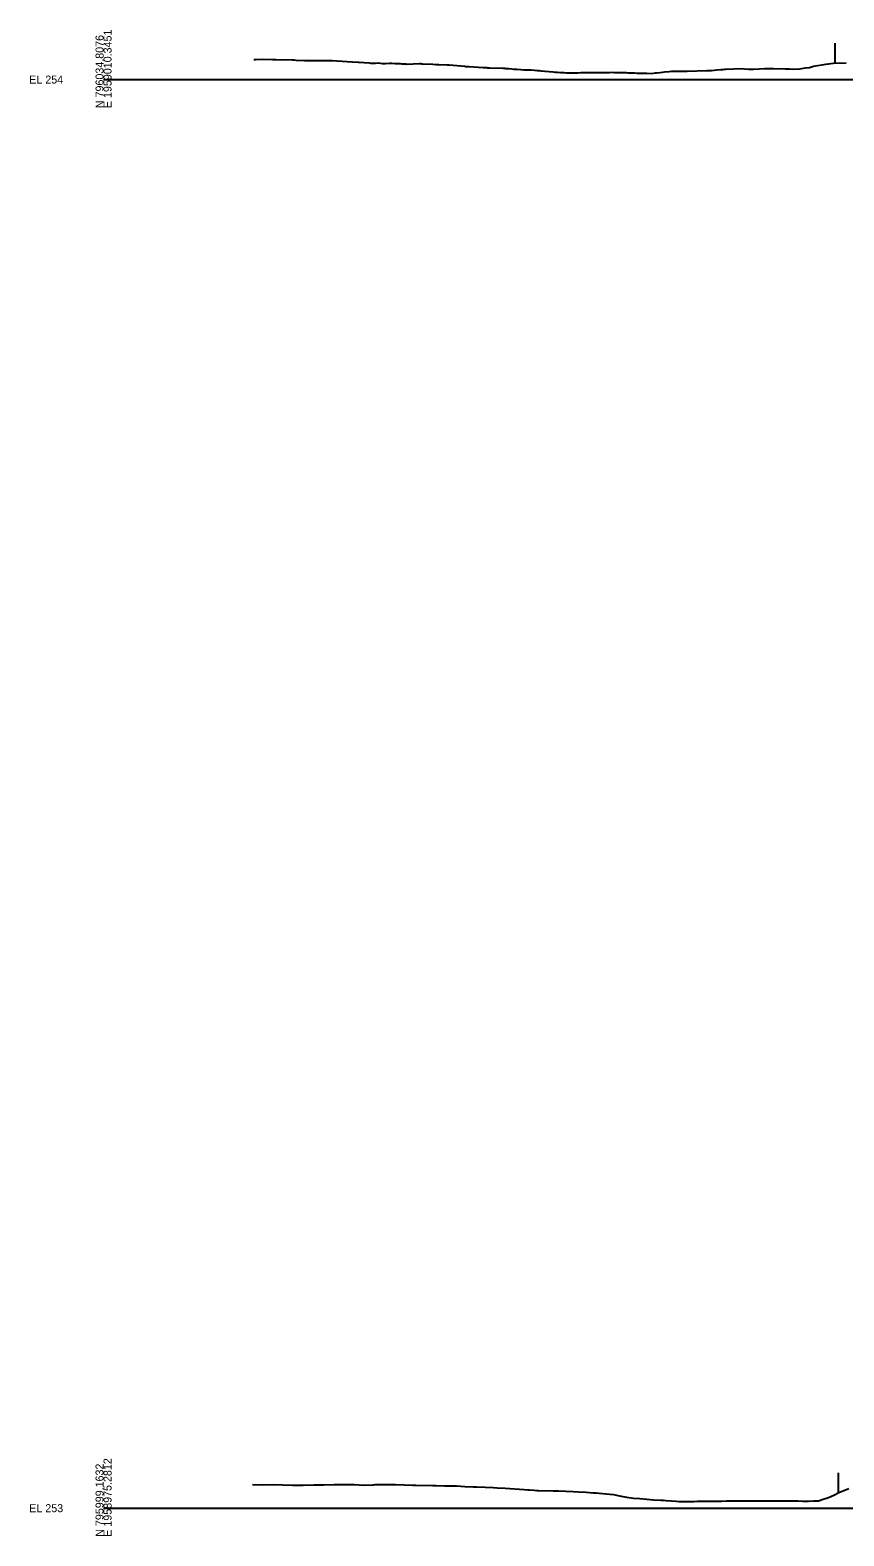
# Model space of a CAD drawing. Extents: x -4026 to 9638, y -10 to 19609.
# Drawn here: x -2026 to -1741, y 14990 to 15517 of the extents above; entities that cross this region are included whole.
import ezdxf

# ---------------------------------------------------------------- set-up
doc = ezdxf.new("R2010")
doc.units = 0
for name, color, linetype in [('Default', 7, 'Continuous'), ('RD_EX_Fence_Other', 7, 'Continuous'), ('RD_GPK_XS_Cell', 7, 'Continuous'), ('RD_XS_ExGround', 7, 'Continuous')]:
    doc.layers.add(name, color=color, linetype=linetype)

msp = doc.modelspace()

# ---------------------------------------------------------------- linework, layer by layer
at = {"layer": 'RD_EX_Fence_Other'}
for p, q in [((-1744.15, 15512.69), (-1744.15, 15505.69)), ((-1742.96, 15012.37), (-1742.96, 15005.37))]:
    msp.add_line(p, q, dxfattribs=at)
at = {"layer": 'RD_GPK_XS_Cell'}
for p, q in [((-2000, 15500), (-1650, 15500)), ((-2000, 15000), (-1650, 15000))]:
    msp.add_line(p, q, dxfattribs=at)
at = {"layer": 'RD_XS_ExGround'}
for points in [[(-1947.42, 15507.05), (-1946.87, 15507.06), (-1943.88, 15507.11), (-1940.94, 15507.03), (-1940.34, 15507.02), (-1939.74, 15507), (-1933.92, 15506.85), (-1933.27, 15506.87), (-1932.61, 15506.79), (-1929.74, 15506.72), (-1926.91, 15506.65), (-1926.2, 15506.65), (-1925.48, 15506.67), (-1919.9, 15506.61), (-1918.35, 15506.53), (-1912.88, 15506.24), (-1910.96, 15506.14), (-1910.57, 15506.09), (-1907.05, 15505.81), (-1906.57, 15505.76), (-1905.78, 15505.75), (-1904.86, 15505.74), (-1903.78, 15505.81), (-1902.5, 15505.63), (-1902.16, 15505.62), (-1901.35, 15505.64), (-1900.05, 15505.7), (-1899.14, 15505.72), (-1897.96, 15505.61), (-1896.98, 15505.59), (-1896.2, 15505.65), (-1895.57, 15505.55), (-1895.03, 15505.53), (-1894.58, 15505.49), (-1894.19, 15505.48), (-1893.86, 15505.44), (-1889.49, 15505.59), (-1889.03, 15505.58), (-1888.63, 15505.52), (-1888.26, 15505.52), (-1884.83, 15505.42), (-1883.77, 15505.32), (-1882.7, 15505.3), (-1879.73, 15505.15), (-1879.43, 15505.13), (-1879.12, 15505.11), (-1873.58, 15504.63), (-1873.28, 15504.61), (-1872.97, 15504.6), (-1872.66, 15504.59), (-1872.34, 15504.57), (-1872.01, 15504.56), (-1867.19, 15504.22), (-1866.89, 15504.2), (-1866.58, 15504.19), (-1866.25, 15504.17), (-1865.92, 15504.16), (-1865.59, 15504.15), (-1865.24, 15504.14), (-1864.88, 15504.13), (-1860.24, 15503.96), (-1859.91, 15503.94), (-1859.58, 15503.93), (-1859.23, 15503.91), (-1858.88, 15503.9), (-1858.51, 15503.85), (-1858.13, 15503.81), (-1857.08, 15503.73), (-1856.39, 15503.64), (-1855.43, 15503.59), (-1853.99, 15503.48), (-1852.91, 15503.41), (-1852.04, 15503.43), (-1850.34, 15503.39), (-1849.2, 15503.28), (-1848.3, 15503.14), (-1847.56, 15503.11), (-1846.94, 15503.09), (-1842.65, 15502.7), (-1841.97, 15502.64), (-1841.15, 15502.58), (-1840.13, 15502.5), (-1838.84, 15502.44), (-1838.03, 15502.36), (-1837.25, 15502.36), (-1835.67, 15502.36), (-1834.44, 15502.39), (-1834.08, 15502.39), (-1833, 15502.41), (-1832.5, 15502.42), (-1831.56, 15502.44), (-1830.92, 15502.44), (-1830.12, 15502.43), (-1829.33, 15502.43), (-1828.68, 15502.45), (-1827.75, 15502.48), (-1827.24, 15502.48), (-1826.16, 15502.49), (-1825.8, 15502.49), (-1824.36, 15502.5), (-1822.92, 15502.52), (-1822.29, 15502.53), (-1821.44, 15502.5), (-1819.78, 15502.48), (-1818.58, 15502.45), (-1818.17, 15502.44), (-1817.13, 15502.43), (-1816.56, 15502.4), (-1815.69, 15502.38), (-1814.96, 15502.34), (-1814.25, 15502.32), (-1813.35, 15502.29), (-1812.81, 15502.28), (-1811.74, 15502.24), (-1811.37, 15502.23), (-1809.93, 15502.2), (-1808.33, 15502.17), (-1806.9, 15502.36), (-1806.51, 15502.38), (-1805.28, 15502.51), (-1804.43, 15502.61), (-1803.67, 15502.69), (-1802.07, 15502.84), (-1801.27, 15502.92), (-1799.91, 15502.91), (-1798.32, 15502.92), (-1797.45, 15502.91), (-1796.88, 15502.91), (-1795.82, 15502.91), (-1788.89, 15503.13), (-1787.22, 15503.19), (-1785.46, 15503.36), (-1783.99, 15503.5), (-1783.16, 15503.56), (-1782.63, 15503.61), (-1782.26, 15503.65), (-1779.62, 15503.79), (-1777.7, 15503.83), (-1775.76, 15503.7), (-1774.17, 15503.67), (-1772.61, 15503.67), (-1770.63, 15503.74), (-1768.63, 15503.84), (-1765.59, 15503.85), (-1761.5, 15503.71), (-1760.03, 15503.72), (-1758.58, 15503.69), (-1756.49, 15503.75), (-1754.37, 15504.09), (-1752.96, 15504.26), (-1751.57, 15504.66), (-1747.24, 15505.37), (-1744.55, 15505.68), (-1740.11, 15505.81)], [(-1947.83, 15008.33), (-1944.29, 15008.22), (-1940.66, 15008.26), (-1933.83, 15008.08), (-1933.53, 15008.07), (-1930.15, 15008.06), (-1926.4, 15008.19), (-1923.08, 15008.15), (-1919.27, 15008.26), (-1912.79, 15008.29), (-1912.14, 15008.27), (-1908.93, 15008.04), (-1905.78, 15008.2), (-1905.4, 15008.23), (-1905.01, 15008.24), (-1901.86, 15008.25), (-1898.77, 15008.28), (-1898.33, 15008.27), (-1897.88, 15008.26), (-1894.79, 15008.2), (-1891.75, 15008.08), (-1890.75, 15008.05), (-1884.74, 15007.95), (-1884.18, 15007.94), (-1883.62, 15007.93), (-1880.65, 15007.85), (-1877.72, 15007.83), (-1876.49, 15007.79), (-1873.58, 15007.64), (-1870.71, 15007.5), (-1870.04, 15007.47), (-1869.36, 15007.44), (-1866.51, 15007.37), (-1863.7, 15007.22), (-1862.23, 15007.15), (-1859.44, 15007.05), (-1852.83, 15006.57), (-1851.53, 15006.45), (-1850.93, 15006.41), (-1849.34, 15006.28), (-1848.39, 15006.23), (-1847.75, 15006.19), (-1842.66, 15006.06), (-1841.76, 15006.04), (-1840.84, 15006.03), (-1838.22, 15005.94), (-1835.64, 15005.82), (-1833.71, 15005.69), (-1831.15, 15005.62), (-1828.63, 15005.4), (-1827.61, 15005.32), (-1826.58, 15005.22), (-1824.08, 15005.05), (-1821.61, 15004.75), (-1820.54, 15004.59), (-1819.45, 15004.32), (-1817.01, 15003.89), (-1814.6, 15003.56), (-1812.32, 15003.4), (-1809.94, 15003.1), (-1807.59, 15002.95), (-1805.02, 15002.82), (-1804.63, 15002.8), (-1804.06, 15002.75), (-1803.16, 15002.69), (-1799.67, 15002.45), (-1798.74, 15002.38), (-1797.47, 15002.32), (-1795.42, 15002.34), (-1793.96, 15002.37), (-1793.38, 15002.38), (-1792.21, 15002.4), (-1791.34, 15002.41), (-1790.44, 15002.42), (-1789.29, 15002.42), (-1788.68, 15002.43), (-1787.26, 15002.45), (-1785, 15002.47), (-1783.78, 15002.49), (-1782.06, 15002.52), (-1781.34, 15002.52), (-1780.11, 15002.54), (-1778.92, 15002.55), (-1778.16, 15002.56), (-1776.19, 15002.59), (-1774.94, 15002.6), (-1773.87, 15002.62), (-1772.15, 15002.61), (-1769.35, 15002.61), (-1766.55, 15002.59), (-1765.78, 15002.57), (-1764.2, 15002.54), (-1760.44, 15002.53), (-1758.49, 15002.52), (-1756.9, 15002.52), (-1755.28, 15002.5), (-1753.37, 15002.5), (-1751.48, 15002.56), (-1749.83, 15002.63), (-1748.15, 15003.17), (-1746.29, 15003.73), (-1744.46, 15004.61), (-1742.76, 15005.47), (-1741.02, 15006.15), (-1739.22, 15006.85)]]:
    msp.add_lwpolyline(points, dxfattribs=at)

# ---------------------------------------------------------------- texts
at = {"layer": 'Default'}
for p in [(-2000, 15500), (-2000, 15000)]:
    msp.add_text('-', height=0.0001, dxfattribs=at).set_placement(p)
at = {"layer": 'RD_GPK_XS_Cell'}
for s, p in [('N 796034.8076', (-2000, 15490)), ('E 1959010.3451', (-1997.2, 15490)), ('N 795999.1632', (-2000, 14990)), ('E 1958975.2812', (-1997.2, 14990))]:
    msp.add_text(s, height=2.8, rotation=90, dxfattribs=at).set_placement(p)
for s, p in [('EL 254', (-2026, 15498.6)), ('EL 253', (-2026, 14998.6))]:
    msp.add_text(s, height=2.8, dxfattribs=at).set_placement(p)

doc.saveas('drawing.dxf')
